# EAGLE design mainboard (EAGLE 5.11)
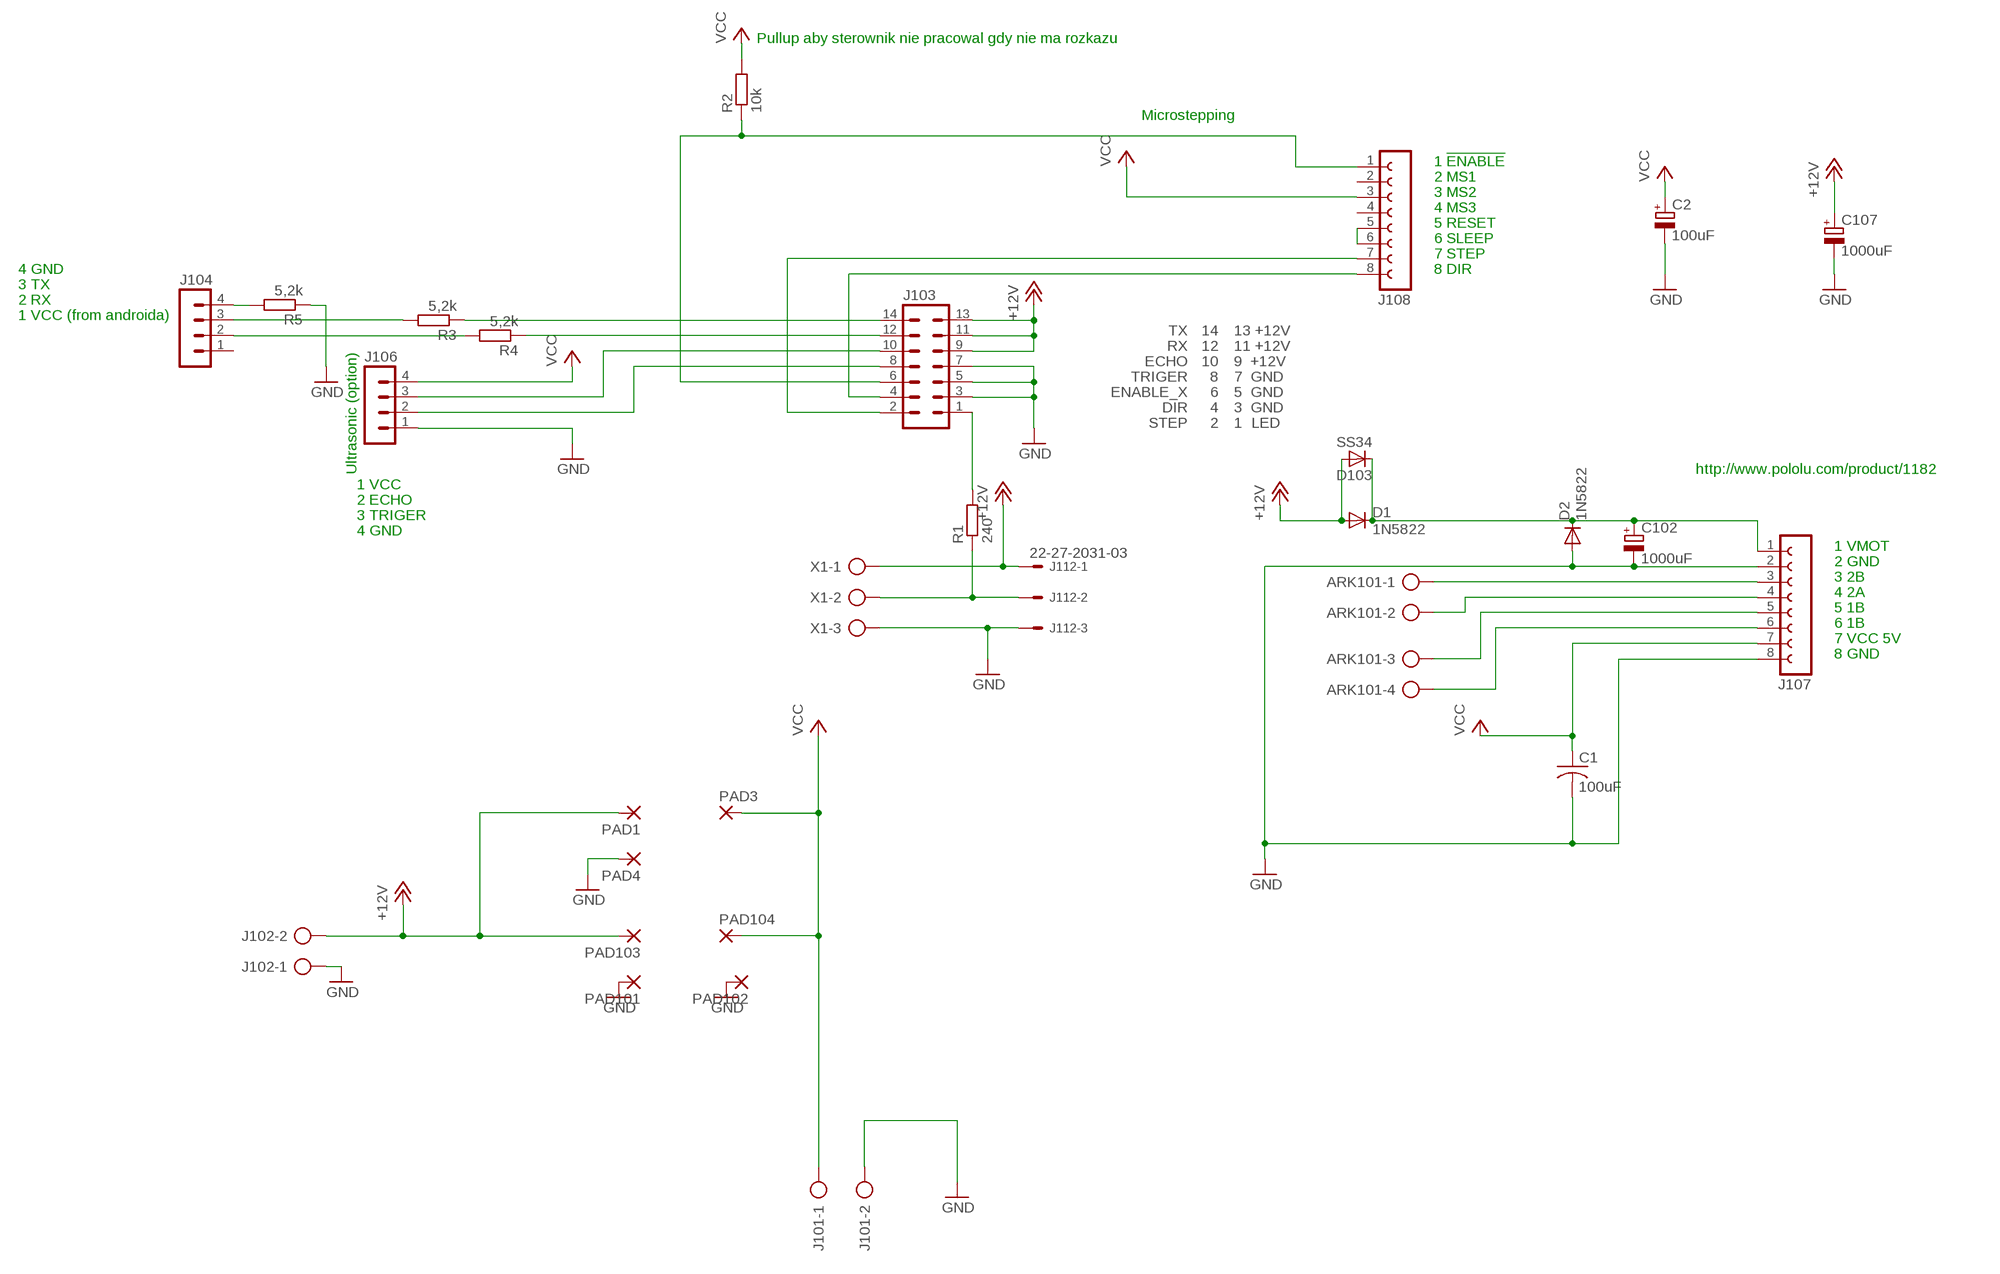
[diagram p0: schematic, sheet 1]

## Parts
ARK101  AK300/4  [AK300/4]
C1  100uF  C-US050-030X075  [C050-030X075]
C2  100uF  CPOL-EUE5-10.5  [E5-10,5]
C102  1000uF  CPOL-EUE5-10.5  [E5-10,5]
C107  1000uF  CPOL-EUE5-10.5  [E5-10,5]
D1  1N5822  DIODE-DO27-15  [DO27-15]
D2  1N5822  DIODE-DO27-15  [DO27-15]
D103  SS34  BYS10  [SOD106A]
J101  AK300/2  [AK300/2]
J102  AK300/2  [AK300/2]
J103  ML14  [ML14]
J104  MA04-1  [MA04-1]
J106  MA04-1  [MA04-1]
J107  FE08-1  [FE08]
J108  FE08-1  [FE08]
J112  22-27-2031-03  [6410-03]
PAD1  3,17/1,1  [3,17/1,1]
PAD3  3,17/1,1  [3,17/1,1]
PAD4  3,17/1,1  [3,17/1,1]
PAD101  3,17/1,1  [3,17/1,1]
PAD102  3,17/1,1  [3,17/1,1]
PAD103  3,17/1,1  [3,17/1,1]
PAD104  3,17/1,1  [3,17/1,1]
R1  240  R-EU_0207/12  [0207/12]
R2  10k  R-EU_0207/12  [0207/12]
R3  5,2k  R-EU_0207/12  [0207/12]
R4  5,2k  R-EU_0207/12  [0207/12]
R5  5,2k  R-EU_0207/12  [0207/12]
X1  AK300/3  [AK300/3]

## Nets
+12V [VCC12V]: C107.+ D1.A D103.A J102.2 J103.9 J103.11 J103.13 J112.1 PAD1.1(P) PAD103.1(P) X1.1
GND [Ground]: C1.2 C2.- C102.- C107.- D2.A J101.2 J102.1 J103.3 J103.5 J103.7 J106.1 J107.2 J107.8 J112.3 PAD4.1(P) PAD101.1(P) PAD102.1(P) R5.1 X1.3
JUMPER101: J103.6 J108.1 R2.1
MISO: J103.4 J108.8
N$1: J103.1 R1.2
N$2: J104.3 R3.2
N$3: J103.2 J108.7
N$4: J112.2 R1.1 X1.2
N$5: J103.10 J106.3
N$6: J103.8 J106.2
N$7: J103.14 R3.1
N$8: J103.12 R4.1
N$9: J104.2 R4.2
N$10: J104.4 R5.2
N$17 [MOTOR]: ARK101.1 J107.3
N$18 [MOTOR]: ARK101.2 J107.4
N$19 [MOTOR]: ARK101.3 J107.5
N$20: ARK101.4 J107.6
N$24: J108.5 J108.6
N$43 [VCC12V]: C102.+ D1.C D2.C D103.K J107.1
VCC: C1.1 C2.+ J101.1 J106.4 J107.7 J108.3 PAD3.1(P) PAD104.1(P) R2.2
Unconnected: J104.1 J108.2 J108.4

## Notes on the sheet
- Pullup aby sterownik nie pracowal gdy nie ma rozkazu
- Microstepping
- 1 !ENABLE
- 2 MS1
- 3 MS2
- 4 MS3
- 5 RESET
- 6 SLEEP
- 7 STEP
- 4 GND | 8 DIR
- 3 TX
- 2 RX
- 1 VCC (from androida)
- TX | 14 | 13 +12V
- RX | 12 | 11 +12V
- ECHO | 10 | 9  +12V
- TRIGER | 8 | 7  GND
- ENABLE_X | 6 | 5  GND
- DIR | 4 | 3  GND
- STEP | 2 | 1 | LED
- Ultrasonic (option) | http://www.pololu.com/product/1182
- 1 VCC
- 2 ECHO
- 3 TRIGER
- 4 GND
- 1 VMOT
- 2 GND
- 3 2B
- 4 2A
- 5 1B
- 6 1B
- 7 VCC 5V
- 8 GND

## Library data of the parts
ARK101 = con-ptr500:AK300/4: CONNECTOR; OC_FARNELL: unknown; OC_NEWARK: unknown
C1 = resistor:C-US: CAPACITOR, American symbol
C2 C102 C107 = rcl:CPOL-EU: POLARIZED CAPACITOR, European symbol
D1 D2 = diode:DIODE-: DIODE
D103 = telefunken:BYS10: DIODE; MPN: BYS10/45; OC_FARNELL: 9549188; OC_NEWARK: 96K7236
J101 J102 = con-ptr500:AK300/2: CONNECTOR; OC_FARNELL: unknown; OC_NEWARK: unknown
J103 = con-ml:ML14: HARTING; OC_FARNELL: unknown; OC_NEWARK: unknown
J104 J106 = con-lstb:MA04-1: PIN HEADER; OC_FARNELL: unknown; OC_NEWARK: unknown
J107 J108 = con-lsta:FE08-1: FEMALE HEADER; OC_FARNELL: unknown; OC_NEWARK: unknown
J112 = con-molex:22-?-03: CONNECTOR wire to board 2.54 mm (.1 inch) pitch header; OC_FARNELL: unknown; OC_NEWARK: unknown
PAD1 PAD3 PAD4 PAD101-PAD104 = wirepad:3,17/1,1: THROUGH-HOLE PAD
R1-R5 = rcl:R-EU_: RESISTOR, European symbol
X1 = con-ptr500:AK300/3: CONNECTOR; OC_FARNELL: unknown; OC_NEWARK: unknown

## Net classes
0 default: width 0.381 mm
1 VCC12V: width 2.54 mm, drill 1.27 mm, clearance 0.508 mm
2 Ground: width 0.508 mm, drill 0.508 mm
3 MOTOR: width 0.813 mm

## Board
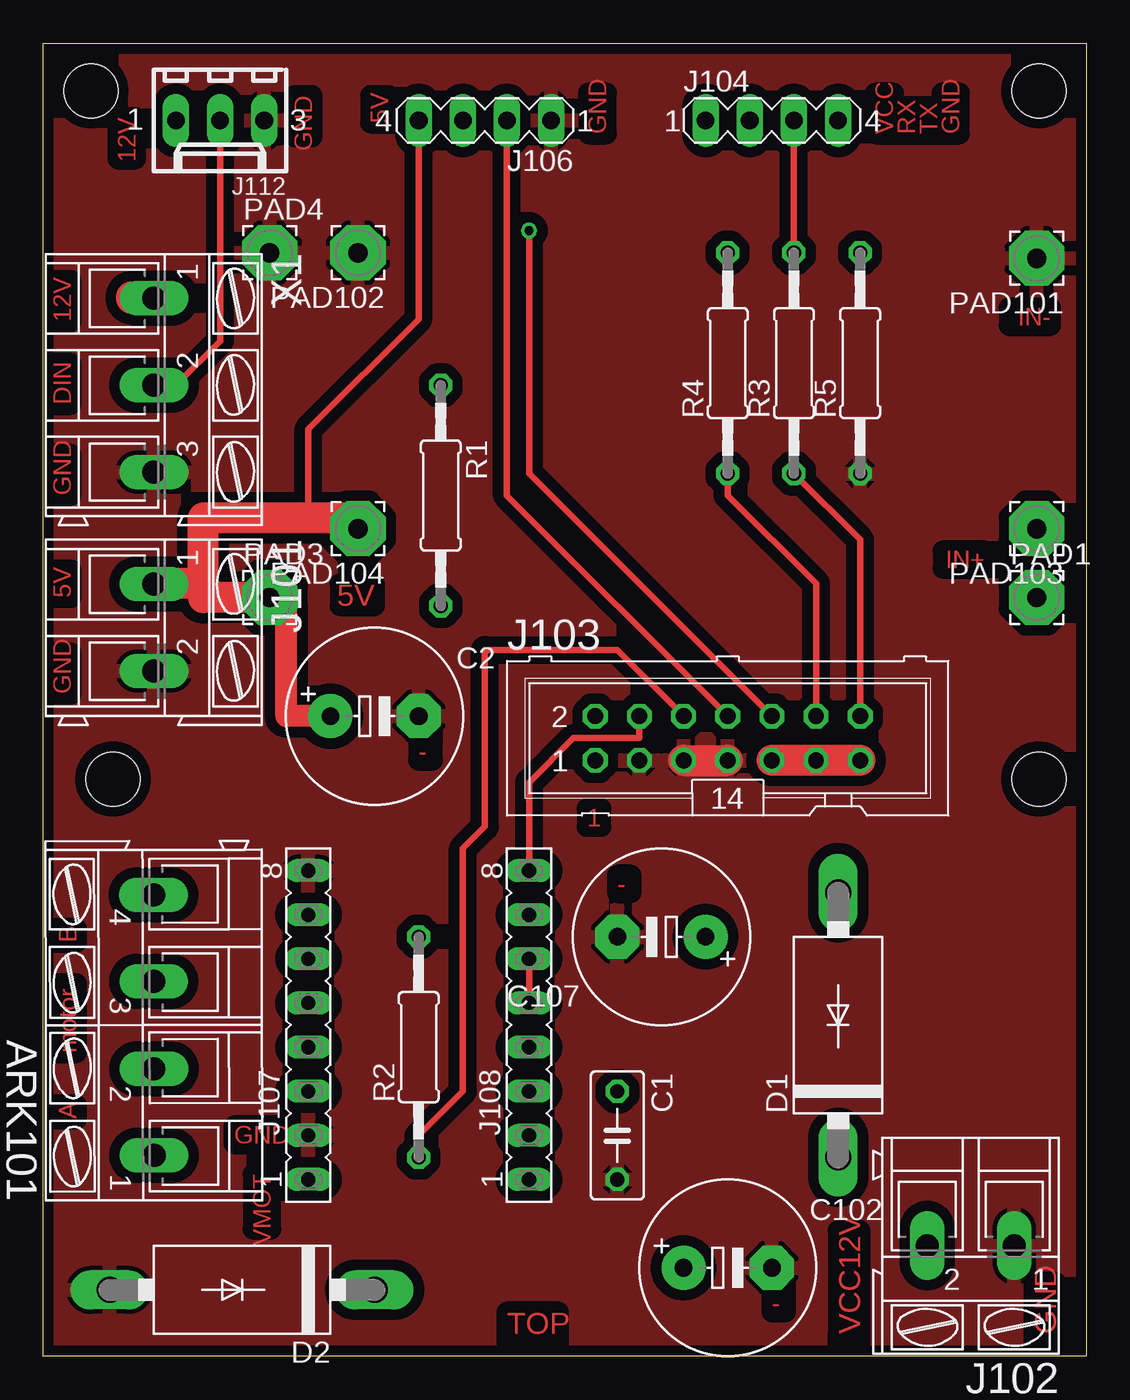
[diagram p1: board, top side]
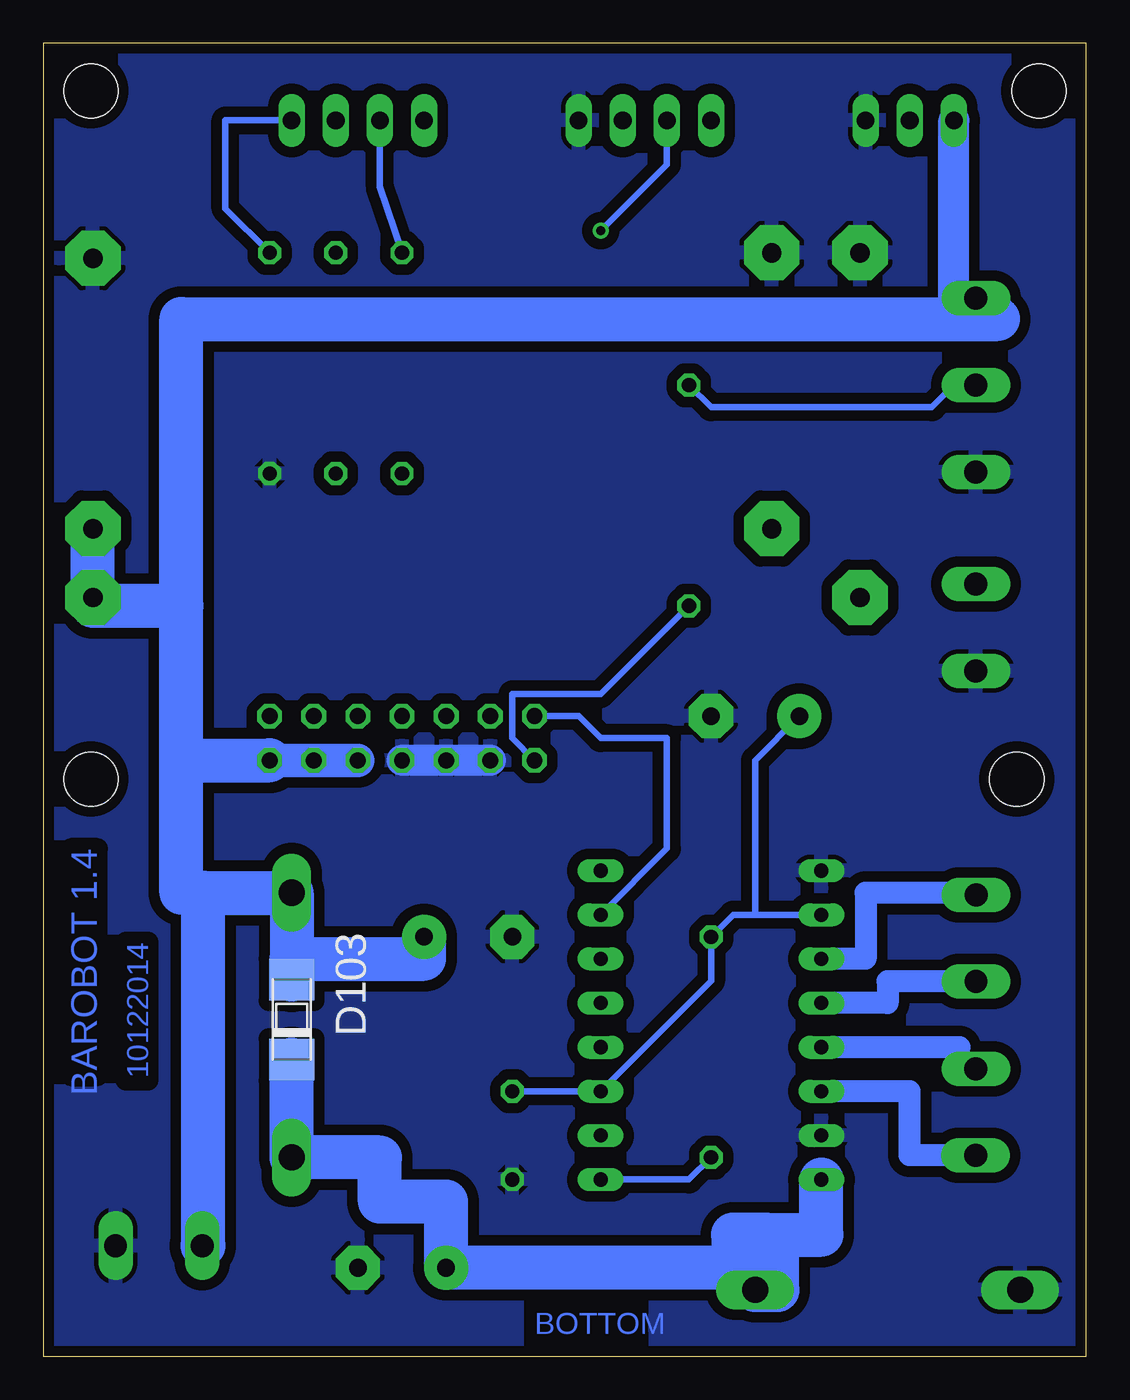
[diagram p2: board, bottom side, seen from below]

Size 60 x 75.55 mm. Coordinates in mm from the lower left corner, seen from the top.
Outline: 0,0 0,75.55 60,75.55 60,0 0,0
Copper layers (1*16): Top 0.035mm / dielectric 1.5mm / Bottom 0.035mm
Design rules "default *": minimum track width 10mil, minimum drill 0.5mm, track to track 8mil, track to pad 8mil, pad to pad 8mil, via to via 8mil, smd to smd 8mil, copper to edge 20mil, drill to drill 8mil, minimum pad ring 10mil, minimum via ring 8mil, stop-mask expansion 4mil, vias tented up to drill 0mil, thermal gap 10mil
Holes 3.1 mm at 4,33.21 57.27,33.21 57.27,72.82 2.73,72.82
tRestrict: area -7.6,69.7 to -5.1,70.2
bRestrict: area 37.5,78.6 to 38.7,81.1

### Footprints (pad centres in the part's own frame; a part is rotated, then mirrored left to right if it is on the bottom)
AK300/4 = drill 1.321 long: 1 -7.493,0; 2 -2.515,0; 3 2.515,0; 4 7.493,0
C050-030X075 = drill 0.813 octagon: 1 -2.54,0; 2 2.54,0
E5-10,5 = drill 1.016 pad 2.54 round: + -2.54,0 | drill 1.016 pad 2.54 octagon: - 2.54,0
DO27-15 = drill 1.499 long: A 7.62,0; C -7.62,0
SOD106A = smd 2.4 x 2.6: A 2.3,0; K -2.3,0
AK300/2 = drill 1.321 long: 1 -2.515,0; 2 2.489,0
ML14 = drill 0.914 octagon: 1 -7.62,-1.27; 2 -7.62,1.27; 3 -5.08,-1.27; 4 -5.08,1.27; 5 -2.54,-1.27; 6 -2.54,1.27; 7 0,-1.27; 8 0,1.27; 9 2.54,-1.27; 10 2.54,1.27; 11 5.08,-1.27; 12 5.08,1.27; 13 7.62,-1.27; 14 7.62,1.27
MA04-1 = drill 1.016 long: 1 -3.81,0; 2 -1.27,0; 3 1.27,0; 4 3.81,0
FE08 = drill 0.813 long: 1 -8.89,0; 2 -6.35,0; 3 -3.81,0; 4 -1.27,0; 5 1.27,0; 6 3.81,0; 7 6.35,0; 8 8.89,0
6410-03 = drill 1.016 long: 1 2.54,0; 2 0,0; 3 -2.54,0
3,17/1,1 = drill 1.118 pad 3.175 octagon: 1 0,0
0207/12 = drill 0.813 octagon: 1 -6.35,0; 2 6.35,0
AK300/3 = drill 1.321 long: 1 -5.004,0; 2 0,0; 3 5.004,0

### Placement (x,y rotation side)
ARK101  6.35,19.05 90.1 top
C1  33.02,12.7 270 top
C2  19.05,36.83 0 top
C102  39.37,5.08 0 top
C107  35.56,24.13 180 top
D1  45.72,19.05 90 top
D2  11.43,3.81 180 top
D103  45.72,19.37 90 bottom
J101  6.35,41.91 270 top
J102  53.34,6.35 180 top
J103  39.37,35.56 0 top
J104  41.91,71.12 0 top
J106  25.4,71.12 180 top
J107  15.24,19.05 90 top
J108  27.94,19.05 90 top
J112  10.16,71.12 180 top
PAD1  57.15,43.66 0 top
PAD3  13.02,43.66 0 top
PAD4  13.02,63.5 0 top
PAD101  57.15,63.18 180 top
PAD102  18.1,63.5 180 top
PAD103  57.15,47.62 180 top
PAD104  18.1,47.62 180 top
R1  22.86,49.53 270 top
R2  21.59,17.78 90 top
R3  43.18,57.15 90 top
R4  39.37,57.15 90 top
R5  46.99,57.15 90 top
X1  6.35,55.88 270 top

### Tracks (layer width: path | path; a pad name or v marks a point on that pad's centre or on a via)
+12V
  Top 1.778: J103.9 J103.11 J103.13 | X1.1 5.08,60.88 5.08,60.96
  Bottom 1.778: 5.08,59.69 6.35,59.69 X1.1 7.62,60.88 J112.1
  Bottom 1.93: J103.13 J103.9
  Bottom 2.54: 5.08,59.69 52.07,59.69 52.07,43.18 | 52.07,34.29 J103.13 | 52.07,34.29 52.07,26.67 50.8,26.67 | 45.72,22.86 D1.A 50.8,26.67 | J102.2 50.8,6.35 50.8,26.67 | 52.07,34.29 52.07,43.18 | 52.07,43.18 57.15,43.18 PAD1.1 PAD103.1 | C107.+ 38.1,22.86 45.72,22.86 | 45.72,22.86 D103.A
GND
  Top 1.778: J103.5 J103.7
  Bottom 1.778: J103.3 J103.5 J103.7
  pour Top (isolate 0.61): 0,74.93 59.69,74.93 59.69,0 0,0
  pour Bottom (isolate 0.61): 0,74.93 59.69,74.93 59.69,0 0,0
JUMPER101
  Top 0.381: J103.6 33.02,40.64 25.4,40.64 25.4,30.48 24.13,29.21 24.13,15.24 21.59,12.7 R2.1
  Bottom 0.381: R2.1 22.86,10.16 J108.1
MISO
  Top 0.381: J108.8 27.94,33.02 30.48,35.56 34.29,35.56 J103.4
N$1
  Bottom 0.381: R1.2 27.94,38.1 33.02,38.1 33.02,35.56 J103.1
N$2
  Top 0.381: R3.2 J104.3
N$3
  Bottom 0.381: J108.7 24.13,29.21 24.13,35.56 27.94,35.56 29.21,36.83 J103.2
N$4
  Top 0.381: J112.2 10.16,58.42 7.62,55.88 X1.2
  Bottom 0.381: R1.1 21.59,54.61 8.89,54.61 7.62,55.88 X1.2
N$5  (via drill 0.5)
  Top 0.381: J103.10 27.94,50.8 v27.94,64.77
  Bottom 0.381: v27.94,64.77 24.13,68.58 J106.3
N$6
  Top 0.381: J103.8 26.67,49.53 J106.2
N$7
  Top 0.381: R3.1 46.99,46.99 J103.14
N$8
  Top 0.381: R4.1 39.37,49.53 44.45,44.45 J103.12
N$9
  Bottom 0.381: R4.2 40.64,67.31 J104.2
N$10
  Bottom 0.381: R5.2 49.53,66.04 49.53,71.12 J104.4
N$17
  Bottom 1.27: J107.3 10.16,15.24 10.16,11.56 ARK101.1
N$18
  Bottom 1.27: J107.4 7.3,17.78 7.3,16.54 ARK101.2
N$19
  Bottom 1.27: J107.5 11.43,20.32 11.43,21.56 ARK101.3
N$20
  Bottom 0.813: ARK101.4 5.08,26.54 5.08,26.67
  Bottom 1.27: J107.6 12.7,22.86 12.7,26.67 5.08,26.67
N$24
  Top 0.381: J108.5 J108.6
N$43
  Bottom 2.54: 18.41,6.99 18.41,6.35 17.78,6.35 17.78,3.81 D2.C | 18.41,6.99 15.24,6.99 J107.1 | D103.K D1.C 40.64,11.43 40.64,8.89 36.83,8.89 C102.+ 20.32,5.08 20.32,6.99 18.41,6.99
VCC
  Top 0.381: J106.4 21.59,59.69 15.24,53.34 15.24,48.26 | 13.97,43.18 PAD3.1
  Top 1.27: C2.+ 13.97,36.83 13.97,43.18
  Top 1.778: 9.21,44.45 6.35,44.45 J101.1 | 9.21,44.45 9.21,48.26 15.24,48.26 18.1,48.26 PAD104.1 | PAD3.1 9.21,43.66 9.21,44.45
  Bottom 0.381: C1.1 J108.3 21.59,21.59 R2.2 20.32,25.4 19.05,25.4 | J107.7 19.05,25.4 | 19.05,25.4 19.05,34.29 C2.+

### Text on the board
Top: GND | 12V | 5V | GND | VCC | RX | TX | GND | IN- | 12V | DIN | GND | IN+ | 5V | 5V | GND | - | 1 | - | B | motor | A | GND | VMOT | - | TOP | VCC12V | GND
Bottom: BAROBOT 1.4 | 10122014 | BOTTOM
